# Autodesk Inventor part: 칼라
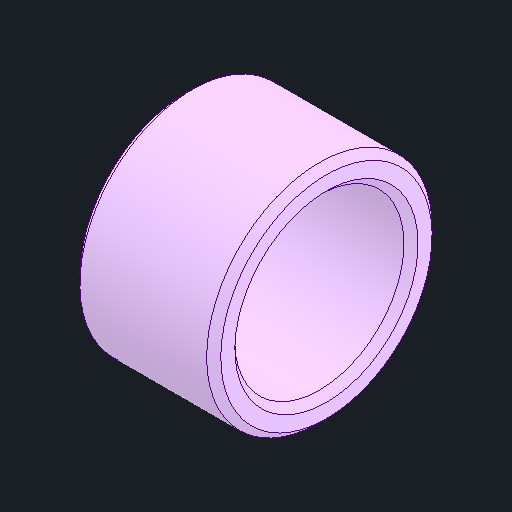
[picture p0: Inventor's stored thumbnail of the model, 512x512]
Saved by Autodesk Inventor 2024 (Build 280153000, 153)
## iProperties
Created: 2024-05
Part Number: 칼라
Material: 강철, 합금
Document SubType Name: Modeling
Designer: kh_501
Density: 7.73 g/cm^3
Appearance: 기본값
Author: jhkim
Sending System: Autodesk Inventor 2025
Preprocessor: ST-DEVELOPER v20
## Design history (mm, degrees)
feature "솔리드1"
node "솔리드2"
